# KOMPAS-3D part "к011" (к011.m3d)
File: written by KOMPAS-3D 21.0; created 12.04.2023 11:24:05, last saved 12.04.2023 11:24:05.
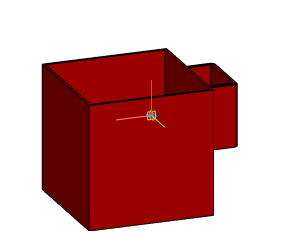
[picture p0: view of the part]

Document properties: Полное имя файла: \\192.168.2.25\новая общая папка\Медиа\Светильники\Кашпо\Кашпо и вазоны\К011\3D\к011.m3d

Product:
- Part/product: к011

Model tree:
1. Операция без истории:1
2. Операция без истории:2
